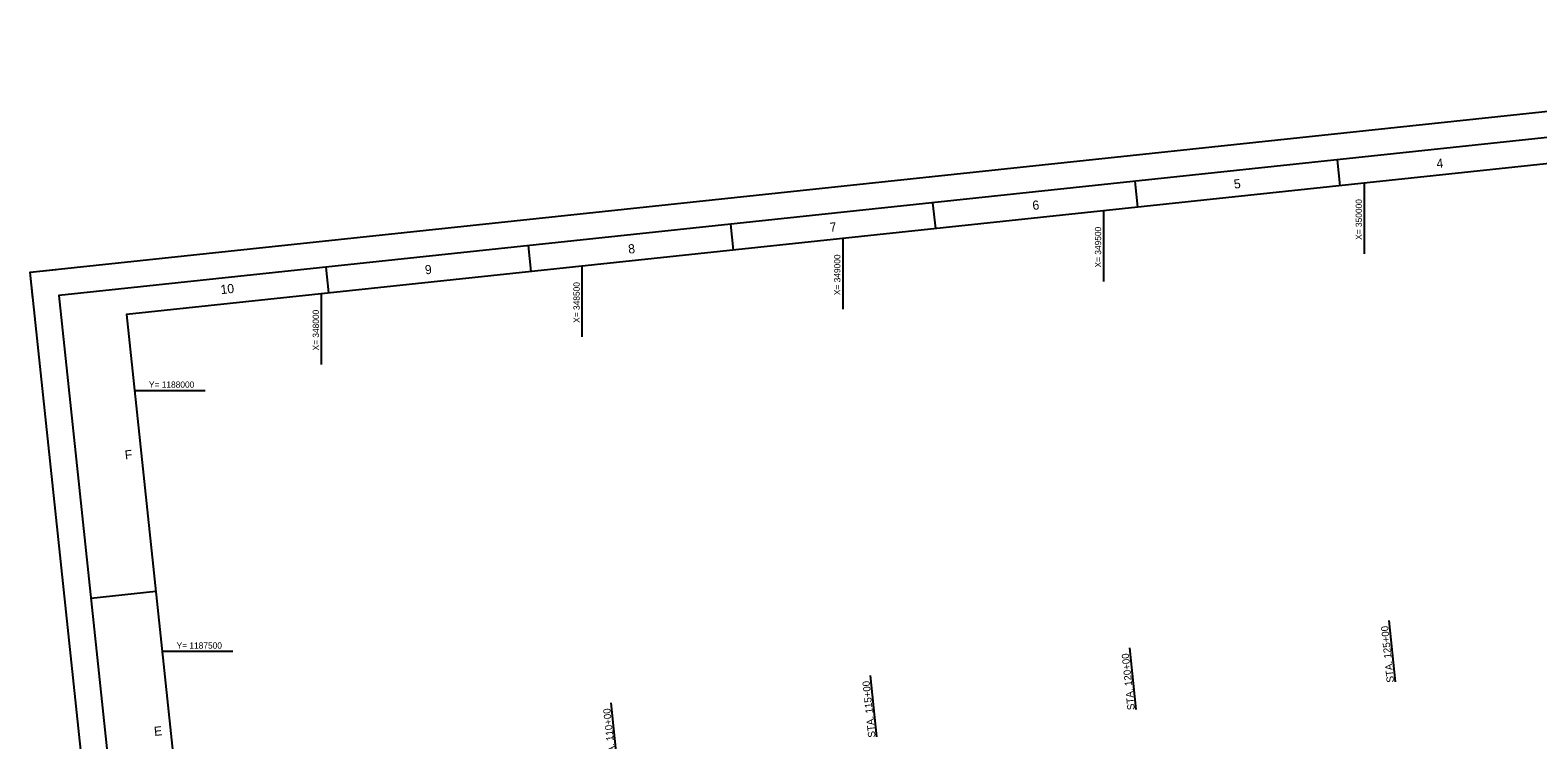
# Model space of a CAD drawing. Extents: x 347441 to 352175, y 1184845 to 1188690.
# Drawn here: x 347441 to 350332, y 1187330 to 1188690 of the extents above; entities that cross this region are included whole.
import ezdxf

# ---------------------------------------------------------------- set-up
doc = ezdxf.new("R2010")
doc.units = 0
for name, color, linetype in [('G-ANNO-NPLT', 7, 'Continuous'), ('G-ANNO-TTLB', 7, 'Continuous'), ('V-ALGN-TEXT', 7, 'Continuous'), ('V-TOPO-COOR-STAT', 7, 'Continuous')]:
    doc.layers.add(name, color=color, linetype=linetype)

msp = doc.modelspace()

# ---------------------------------------------------------------- linework, layer by layer
at = {"layer": 'G-ANNO-NPLT'}
msp.add_lwpolyline([(347441.2, 1188226.4), (351816.7, 1188690.2), (352175, 1185309.2), (347799.6, 1184845.4)], close=True, dxfattribs=at)
msp.add_lwpolyline([(347446.5, 1188176.7), (347441.2, 1188226.4), (347490.9, 1188231.7)], dxfattribs=at)
at = {"layer": 'G-ANNO-TTLB'}
for p, q in [((349947.5, 1188441.8), (349952.7, 1188392.1)), ((349559.6, 1188400.7), (349564.9, 1188351)), ((349171.8, 1188359.6), (349177.1, 1188309.9)), ((348784, 1188318.5), (348789.2, 1188268.8)), ((348396.1, 1188277.4), (348401.4, 1188227.7)), ((348396.1, 1188277.4), (348401.4, 1188227.7)), ((348008.3, 1188236.3), (348013.6, 1188186.6)), ((347557.7, 1187601.7), (347682, 1187614.9))]:
    msp.add_line(p, q, dxfattribs=at)
for points in [[(347844, 1184900.4), (352120.1, 1185353.6), (351772.2, 1188635.2), (347496.2, 1188182)], [(351727.8, 1188580.2), (347625.8, 1188145.4), (347963.1, 1184963.3), (352065.1, 1185398.1)]]:
    msp.add_lwpolyline(points, close=True, dxfattribs=at)
at = {"layer": 'V-ALGN-TEXT'}
for p, q in [((350059.5, 1187441.1), (350047, 1187559)), ((349562.3, 1187388.4), (349549.8, 1187506.3)), ((349065.1, 1187335.7), (349052.6, 1187453.6)), ((348567.8, 1187283), (348555.4, 1187400.9))]:
    msp.add_line(p, q, dxfattribs=at)
at = {"layer": 'V-TOPO-COOR-STAT'}
for p, q in [((350000, 1188261.3), (350000, 1188397.1)), ((349500, 1188208.4), (349500, 1188344.1)), ((349000, 1188155.4), (349000, 1188291.1)), ((348500, 1188102.4), (348500, 1188238.1)), ((348000, 1188049.4), (348000, 1188185.1)), ((347641.2, 1188000), (347776.9, 1188000)), ((347694.2, 1187500), (347829.9, 1187500))]:
    msp.add_line(p, q, dxfattribs=at)

# ---------------------------------------------------------------- texts
at = {"layer": 'G-ANNO-TTLB'}
for s, p in [('4', (350138.9, 1188425.7)), ('5', (349750.4, 1188386.4)), ('6', (349364.1, 1188345.5)), ('7', (348975.4, 1188303.6)), ('8', (348589, 1188261.9)), ('9', (348199.2, 1188222.2)), ('10', (347807.2, 1188184.2)), ('F', (347623.6, 1187867.3)), ('E', (347679.6, 1187337.6))]:
    msp.add_text(s, height=17.5, rotation=6.0506, dxfattribs=at).set_placement(p)
at = {"layer": 'V-ALGN-TEXT'}
for s, p in [('STA. 125+00', (350056.7, 1187440.7)), ('STA. 120+00', (349559.5, 1187388)), ('STA. 115+00', (349062.3, 1187335.3)), ('STA. 110+00', (348565.1, 1187282.6))]:
    msp.add_text(s, height=13.92, rotation=96.0506, dxfattribs=at).set_placement(p)
at = {"layer": 'V-TOPO-COOR-STAT'}
for s, p in [('X= 350000', (349995, 1188288.4)), ('X= 349500', (349495, 1188235.4)), ('X= 349000', (348995, 1188182.4)), ('X= 348500', (348495, 1188129.4)), ('X= 348000', (347995, 1188076.4))]:
    msp.add_text(s, height=12, rotation=90, dxfattribs=at).set_placement(p)
for s, p in [('Y= 1188000', (347669, 1188005)), ('Y= 1187500', (347722, 1187505))]:
    msp.add_text(s, height=12, dxfattribs=at).set_placement(p)

doc.saveas('drawing.dxf')
